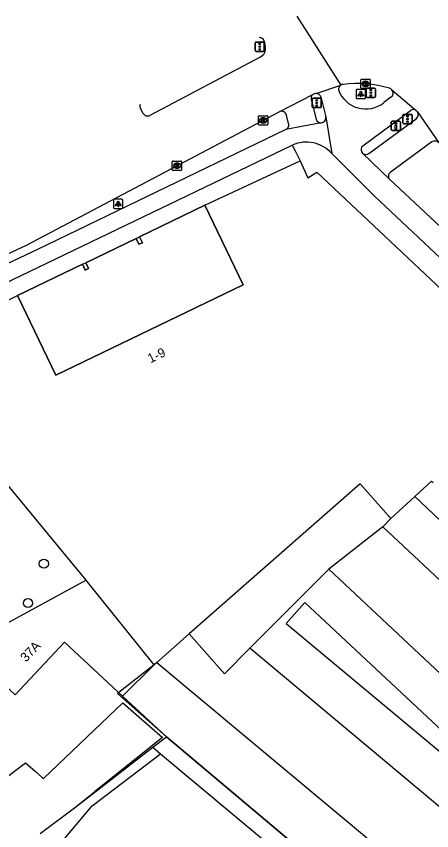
# Model space of a CAD drawing. Extents: x 160107 to 160928, y 382056 to 382918.
# Drawn here: x 160821.8 to 160866.4, y 382827.7 to 382915.3 of the extents above; entities that cross this region are included whole.
import ezdxf

# ---------------------------------------------------------------- set-up
doc = ezdxf.new("R2010")
doc.units = 0
for name, color, linetype in [('IMGEO_Boom', 7, 'Continuous'), ('IMGEO_Drukknoppaal', 7, 'Continuous'), ('IMGEO_Fietspad_gesloten', 7, 'Continuous'), ('IMGEO_Hek', 7, 'Continuous'), ('IMGEO_Kolk', 7, 'Continuous'), ('IMGEO_Lichtpunt', 7, 'Continuous'), ('IMGEO_Muur', 7, 'Continuous'), ('IMGEO_Pand', 7, 'Continuous'), ('IMGEO_Pand_nummerreeks', 7, 'Continuous'), ('IMGEO_Pand_overbouw', 7, 'Continuous'), ('IMGEO_Parkeervlak_open', 7, 'Continuous'), ('IMGEO_Rijbaan_lokaal_gesloten', 7, 'Continuous'), ('IMGEO_Rijbaan_lokaal_open', 7, 'Continuous'), ('IMGEO_Verkeersregelinstallatiepaal', 7, 'Continuous'), ('IMGEO_Voetpad_gesloten', 7, 'Continuous'), ('IMGEO_Voetpad_open', 7, 'Continuous')]:
    doc.layers.add(name, color=color, linetype=linetype)

msp = doc.modelspace()

# ---------------------------------------------------------------- linework, layer by layer
at = {"layer": 'IMGEO_Boom'}
for centre in [(160824.732, 382856.436), (160823.02, 382852.195)]:
    msp.add_circle(centre, 0.489, dxfattribs=at)
at = {"layer": 'IMGEO_Drukknoppaal'}
for p, q in [((160862.088, 382903.149), (160862.088, 382903.949)), ((160862.088, 382903.949), (160862.088, 382903.149)), ((160862.188, 382904.049), (160862.978, 382904.049)), ((160862.978, 382904.049), (160862.188, 382904.049)), ((160863.078, 382903.949), (160863.078, 382903.149)), ((160863.078, 382903.149), (160863.078, 382903.949)), ((160862.978, 382903.049), (160862.188, 382903.049)), ((160862.188, 382903.049), (160862.978, 382903.049))]:
    msp.add_line(p, q, dxfattribs=at)
msp.add_lwpolyline([(160862.658, 382903.674), (160862.658, 382903.174), (160862.508, 382903.174), (160862.508, 382903.674), (160862.658, 382903.674)], dxfattribs=at)
msp.add_circle((160862.583, 382903.839), 0.085, dxfattribs=at)
for centre, start, end in [((160862.188, 382903.949), 90, 180), ((160862.188, 382903.949), 90, 180), ((160862.978, 382903.949), 0, 90), ((160862.978, 382903.949), 360, 90), ((160862.188, 382903.149), 180, 270), ((160862.188, 382903.149), 180, 270), ((160862.978, 382903.149), 270, 0), ((160862.978, 382903.149), 270, 0)]:
    msp.add_arc(centre, 0.1, start, end, dxfattribs=at)
at = {"layer": 'IMGEO_Fietspad_gesloten'}
for points in [[(160854.521, 382906.665), (160855.067, 382904.509)], [(160862.061, 382906.639), (160861.286, 382906.048)], [(160855.067, 382904.509), (160855.706, 382900.56)], [(160859.033, 382901.418), (160864.171, 382905.21)], [(160854.566, 382903.866), (160850.751, 382903.174)], [(160850.751, 382903.174), (160824.044, 382890.246), (160820.773, 382888.699), (160818.211, 382887.624)], [(160820.429, 382886.565), (160851.435, 382901.477)], [(160907.683, 382851.452), (160880.807, 382876.637), (160876.3, 382880.906), (160860.259, 382896.037), (160855.706, 382900.56)], [(160859.046, 382900.582), (160858.953, 382900.672)], [(160861.894, 382897.82), (160859.046, 382900.582)], [(160908.09, 382854.364), (160881.279, 382879.654), (160861.894, 382897.82)]]:
    msp.add_lwpolyline(points, dxfattribs=at)
for centre, radius, start, end in [((160856.968, 382907.472), 0.546, 121.21267, 184.94604), ((160854.005, 382906.491), 0.545, 18.66756, 87.88894), ((160859.346, 382908.471), 3.104, 199.70196, 308.67201), ((160861.744, 382907.076), 0.54, 305.92504, 39.64461), ((160864.467, 382904.762), 0.537, 54.27107, 123.47496), ((160854.456, 382904.468), 0.612, 280.35139, 3.8), ((160852.947, 382898.114), 3.687, 41.55965, 114.20503), ((160859.371, 382901.004), 0.534, 129.28473, 218.47342)]:
    msp.add_arc(centre, radius, start, end, dxfattribs=at)
at = {"layer": 'IMGEO_Hek'}
for points in [[(160836.59, 382845.555), (160832.666, 382842.466)], [(160832.666, 382842.466), (160837.913, 382837.822)]]:
    msp.add_lwpolyline(points, dxfattribs=at)
at = {"layer": 'IMGEO_Kolk'}
for p, q in [((160858.832, 382907.642), (160858.832, 382908.494)), ((160858.907, 382908.568), (160859.759, 382908.568)), ((160859.32, 382908.348), (160859.345, 382908.348)), ((160859.833, 382908.494), (160859.833, 382907.642)), ((160859.759, 382907.568), (160858.907, 382907.568)), ((160859.343, 382907.788), (160859.318, 382907.788)), ((160847.815, 382903.71), (160847.815, 382904.562)), ((160847.89, 382904.636), (160848.742, 382904.636)), ((160848.303, 382904.416), (160848.328, 382904.416)), ((160848.816, 382904.562), (160848.816, 382903.71)), ((160848.742, 382903.636), (160847.89, 382903.636)), ((160848.326, 382903.856), (160848.301, 382903.856)), ((160838.548, 382898.837), (160838.548, 382899.689)), ((160838.623, 382899.763), (160839.475, 382899.763)), ((160839.036, 382899.543), (160839.061, 382899.543)), ((160839.549, 382899.689), (160839.549, 382898.837)), ((160839.475, 382898.763), (160838.623, 382898.763)), ((160839.059, 382898.983), (160839.034, 382898.983))]:
    msp.add_line(p, q, dxfattribs=at)
for points in [[(160858.832, 382907.642), (160858.832, 382908.494)], [(160858.907, 382908.568), (160859.759, 382908.568)], [(160859.153, 382908.268), (160859.276, 382908.268), (160859.276, 382908.117), (160859.406, 382908.268), (160859.57, 382908.268), (160859.424, 382908.117), (160859.577, 382907.868), (160859.425, 382907.868), (160859.34, 382908.032), (160859.276, 382907.965), (160859.276, 382907.868), (160859.153, 382907.868), (160859.153, 382908.268)], [(160859.833, 382908.494), (160859.833, 382907.642)], [(160859.759, 382907.568), (160858.907, 382907.568)], [(160847.815, 382903.71), (160847.815, 382904.562)], [(160847.89, 382904.636), (160848.742, 382904.636)], [(160848.816, 382904.562), (160848.816, 382903.71)], [(160848.742, 382903.636), (160847.89, 382903.636)], [(160848.136, 382904.336), (160848.259, 382904.336), (160848.259, 382904.185), (160848.389, 382904.336), (160848.553, 382904.336), (160848.407, 382904.185), (160848.56, 382903.936), (160848.408, 382903.936), (160848.323, 382904.1), (160848.259, 382904.033), (160848.259, 382903.936), (160848.136, 382903.936), (160848.136, 382904.336)], [(160838.548, 382898.837), (160838.548, 382899.689)], [(160838.623, 382899.763), (160839.475, 382899.763)], [(160838.869, 382899.463), (160838.992, 382899.463), (160838.992, 382899.312), (160839.122, 382899.463), (160839.286, 382899.463), (160839.14, 382899.312), (160839.293, 382899.063), (160839.141, 382899.063), (160839.056, 382899.227), (160838.992, 382899.16), (160838.992, 382899.063), (160838.869, 382899.063), (160838.869, 382899.463)], [(160839.549, 382899.689), (160839.549, 382898.837)], [(160839.475, 382898.763), (160838.623, 382898.763)]]:
    msp.add_lwpolyline(points, dxfattribs=at)
for centre, start, end in [((160858.909, 382908.492), 91.55205, 178.44795), ((160858.909, 382908.492), 91.55205, 178.44795), ((160859.757, 382908.492), 1.55205, 88.44795), ((160859.757, 382908.492), 1.55205, 88.44795), ((160858.909, 382907.644), 181.55205, 268.44795), ((160858.909, 382907.644), 181.55205, 268.44795), ((160859.757, 382907.644), 271.55205, 358.44795), ((160859.757, 382907.644), 271.55205, 358.44795), ((160847.892, 382904.56), 91.55205, 178.44795), ((160847.892, 382904.56), 91.55205, 178.44795), ((160848.74, 382904.56), 1.55205, 88.44795), ((160848.74, 382904.56), 1.55205, 88.44795), ((160847.892, 382903.712), 181.55205, 268.44795), ((160847.892, 382903.712), 181.55205, 268.44795), ((160848.74, 382903.712), 271.55205, 358.44795), ((160848.74, 382903.712), 271.55205, 358.44795), ((160838.625, 382899.687), 91.55205, 178.44795), ((160838.625, 382899.687), 91.55205, 178.44795), ((160839.473, 382899.687), 1.55205, 88.44795), ((160839.473, 382899.687), 1.55205, 88.44795), ((160838.625, 382898.839), 181.55205, 268.44795), ((160838.625, 382898.839), 181.55205, 268.44795), ((160839.473, 382898.839), 271.55205, 358.44795), ((160839.473, 382898.839), 271.55205, 358.44795)]:
    msp.add_arc(centre, 0.0765, start, end, dxfattribs=at)
for centre, major_axis, ratio, start_param, end_param in [((160859.319, 382908.068), (-0.387, 0.002), 0.722429, 4.712389, 7.853982), ((160859.344, 382908.068), (-0.39, 0.002), 0.717154, 1.570796, 4.712389), ((160848.302, 382904.136), (-0.387, 0.002), 0.722429, 4.712389, 7.853982), ((160848.327, 382904.136), (-0.39, 0.002), 0.717154, 1.570796, 4.712389), ((160839.035, 382899.263), (-0.387, 0.002), 0.722429, 4.712389, 7.853982), ((160839.06, 382899.263), (-0.39, 0.002), 0.717154, 1.570796, 4.712389)]:
    msp.add_ellipse(centre, major_axis=major_axis, ratio=ratio, start_param=start_param, end_param=end_param, dxfattribs=at)
at = {"layer": 'IMGEO_Lichtpunt'}
for p, q in [((160858.312, 382907.38), (160858.312, 382906.573)), ((160858.312, 382907.38), (160858.312, 382906.573)), ((160859.214, 382907.475), (160858.406, 382907.475)), ((160859.214, 382907.475), (160858.406, 382907.475)), ((160859.308, 382906.573), (160859.308, 382907.38)), ((160859.308, 382906.573), (160859.308, 382907.38)), ((160858.406, 382906.479), (160859.214, 382906.479)), ((160858.406, 382906.479), (160859.214, 382906.479)), ((160833.134, 382895.651), (160832.326, 382895.651)), ((160833.134, 382895.651), (160832.326, 382895.651)), ((160832.232, 382895.556), (160832.232, 382894.749)), ((160832.232, 382895.556), (160832.232, 382894.749)), ((160833.228, 382894.749), (160833.228, 382895.556)), ((160833.228, 382894.749), (160833.228, 382895.556)), ((160832.326, 382894.655), (160833.134, 382894.655)), ((160832.326, 382894.655), (160833.134, 382894.655))]:
    msp.add_line(p, q, dxfattribs=at)
for points in [[(160858.686, 382907.044), (160858.725, 382907.016), (160858.537, 382906.754), (160858.499, 382906.781), (160858.686, 382907.044)], [(160858.788, 382906.996), (160858.835, 382906.996), (160858.835, 382906.674), (160858.788, 382906.674), (160858.788, 382906.996)], [(160858.898, 382907.016), (160858.936, 382907.043), (160859.123, 382906.781), (160859.084, 382906.753), (160858.898, 382907.016)], [(160832.606, 382895.22), (160832.645, 382895.192), (160832.457, 382894.93), (160832.419, 382894.957), (160832.606, 382895.22)], [(160832.708, 382895.172), (160832.755, 382895.172), (160832.755, 382894.85), (160832.708, 382894.85), (160832.708, 382895.172)], [(160832.818, 382895.192), (160832.856, 382895.219), (160833.043, 382894.957), (160833.004, 382894.929), (160832.818, 382895.192)]]:
    msp.add_lwpolyline(points, dxfattribs=at)
for centre in [(160858.811, 382907.178), (160832.731, 382895.354)]:
    msp.add_circle(centre, 0.0994, dxfattribs=at)
for centre, start, end in [((160858.406, 382907.38), 90, 180), ((160858.406, 382907.38), 90, 180), ((160859.214, 382907.38), 0, 90), ((160859.214, 382907.38), 0, 90), ((160858.406, 382906.573), 180, 270), ((160858.406, 382906.573), 180, 270), ((160859.214, 382906.573), 270, 0), ((160859.214, 382906.573), 270, 360), ((160832.326, 382895.556), 90, 180), ((160832.326, 382895.556), 90, 180), ((160833.134, 382895.556), 0, 90), ((160833.134, 382895.556), 0, 90), ((160832.326, 382894.749), 180, 270), ((160832.326, 382894.749), 180, 270), ((160833.134, 382894.749), 270, 0), ((160833.134, 382894.749), 270, 360)]:
    msp.add_arc(centre, 0.0946, start, end, dxfattribs=at)
at = {"layer": 'IMGEO_Muur'}
for points in [[(160837.913, 382837.822), (160861.483, 382817.978)], [(160828.158, 382830.281), (160836.442, 382836.685)], [(160836.442, 382836.685), (160837.27, 382835.986)]]:
    msp.add_lwpolyline(points, dxfattribs=at)
at = {"layer": 'IMGEO_Pand'}
for points in [[(160842.054, 382895.005), (160852.299, 382899.776)], [(160852.299, 382899.776), (160853.109, 382897.965), (160854.082, 382898.574), (160875.468, 382878.428)], [(160842.054, 382895.005), (160846.177, 382886.446), (160826.022, 382876.74), (160821.899, 382885.299)], [(160834.66, 382891.435), (160835.021, 382891.609)], [(160834.66, 382891.435), (160834.964, 382890.804), (160835.324, 382890.978), (160835.021, 382891.609)], [(160828.874, 382888.653), (160829.235, 382888.827)], [(160828.874, 382888.653), (160829.178, 382888.022), (160829.538, 382888.196), (160829.235, 382888.827)], [(160811.707, 382880.282), (160821.899, 382885.299)], [(160829.281, 382854.653), (160817.486, 382868.952), (160817.086, 382869.61)], [(160862.028, 382861.283), (160858.731, 382865.029), (160840.366, 382848.876)], [(160866.606, 382865.137), (160866.424, 382865.309), (160864.631, 382863.667)], [(160864.631, 382863.667), (160862.028, 382861.283)], [(160829.281, 382854.653), (160818.676, 382848.872)], [(160836.59, 382845.555), (160829.388, 382854.523), (160829.281, 382854.653)], [(160840.366, 382848.876), (160836.872, 382845.803)], [(160816.125, 382847.481), (160821.642, 382842.326), (160826.951, 382848.006), (160833.184, 382842.181)], [(160836.872, 382845.803), (160836.59, 382845.555)], [(160833.184, 382842.181), (160836.59, 382845.555)], [(160813.461, 382827.975), (160822.775, 382834.996), (160823.797, 382834.101), (160824.507, 382833.479), (160824.682, 382833.325), (160833.239, 382841.46), (160837.501, 382837.727), (160830.181, 382831.893)], [(160826.177, 382825.89), (160829.915, 382830.38), (160837.27, 382835.986)], [(160837.27, 382835.986), (160869.624, 382808.98), (160869.704, 382809.079), (160878.006, 382802.366)], [(160824.354, 382827.401), (160828.158, 382830.281), (160830.181, 382831.893)]]:
    msp.add_lwpolyline(points, dxfattribs=at)
at = {"layer": 'IMGEO_Pand_overbouw'}
msp.add_lwpolyline([(160834.66, 382891.435), (160829.235, 382888.827), (160829.538, 382888.196), (160829.178, 382888.022), (160828.874, 382888.653), (160821.899, 382885.299), (160826.022, 382876.74), (160846.177, 382886.446), (160842.054, 382895.005), (160835.021, 382891.609), (160835.324, 382890.978), (160834.964, 382890.804)], close=True, dxfattribs=at)
at = {"layer": 'IMGEO_Parkeervlak_open'}
for points in [[(160885.141, 382837.99), (160888.24, 382841.299), (160864.631, 382863.667)], [(160850.806, 382850.011), (160873.79, 382830.829), (160874.703, 382831.786), (160852.792, 382852.262), (160850.806, 382850.011)]]:
    msp.add_lwpolyline(points, dxfattribs=at)
at = {"layer": 'IMGEO_Rijbaan_lokaal_gesloten'}
for points in [[(160851.95, 382915.343), (160856.685, 382907.939)], [(160848.428, 382912.674), (160848.544, 382912.085)], [(160848.047, 382910.983), (160836.138, 382904.677)], [(160854.025, 382907.035), (160856.685, 382907.939)], [(160862.16, 382907.421), (160864.781, 382905.198)], [(160850.096, 382905.089), (160853.659, 382906.91)], [(160835.422, 382904.898), (160835.125, 382905.413)], [(160817.861, 382888.575), (160820.869, 382889.792), (160822.883, 382890.72), (160850.096, 382905.089)], [(160864.911, 382905.064), (160867.193, 382901.716)]]:
    msp.add_lwpolyline(points, dxfattribs=at)
for centre, radius, start, end in [((160847.918, 382912.533), 0.521, 94.83979, 94.89905), ((160847.923, 382912.529), 0.525, 16.03297, 95.35477), ((160847.584, 382911.855), 0.987, 297.95346, 13.49597), ((160856.96, 382907.486), 0.53, 96.20797, 121.29154), ((160858.395, 382895.807), 12.297, 73.45946, 96.96958), ((160854.008, 382906.487), 0.548, 88.19084, 129.52231), ((160861.746, 382907.081), 0.536, 39.45108, 73.77189), ((160835.521, 382905.677), 0.476, 156.9739, 213.70009), ((160835.89, 382905.145), 0.529, 207.77626, 297.9171), ((160864.48, 382904.776), 0.518, 33.74544, 54.51845)]:
    msp.add_arc(centre, radius, start, end, dxfattribs=at)
at = {"layer": 'IMGEO_Rijbaan_lokaal_open'}
for points in [[(160861.201, 382860.414), (160855.371, 382855.843)], [(160885.141, 382837.99), (160861.201, 382860.414)], [(160855.371, 382855.843), (160882.262, 382830.641), (160875.839, 382823.088), (160846.893, 382847.344)], [(160846.893, 382847.344), (160844.141, 382844.584), (160840.366, 382848.876)], [(160836.872, 382845.803), (160865.06, 382822.273), (160865.612, 382822.936), (160869.325, 382819.842)], [(160837.913, 382837.822), (160833.184, 382842.181)], [(160836.442, 382836.685), (160837.913, 382837.822)], [(160830.181, 382831.893), (160830.204, 382831.863), (160836.442, 382836.685)]]:
    msp.add_lwpolyline(points, dxfattribs=at)
at = {"layer": 'IMGEO_Verkeersregelinstallatiepaal'}
for p, q in [((160847.449, 382911.671), (160847.449, 382912.471)), ((160847.449, 382912.471), (160847.449, 382911.671)), ((160847.549, 382912.571), (160848.339, 382912.571)), ((160848.339, 382912.571), (160847.549, 382912.571)), ((160848.439, 382912.471), (160848.439, 382911.671)), ((160848.439, 382911.671), (160848.439, 382912.471)), ((160848.339, 382911.571), (160847.549, 382911.571)), ((160847.549, 382911.571), (160848.339, 382911.571)), ((160859.4, 382906.713), (160859.4, 382907.513)), ((160859.4, 382907.513), (160859.4, 382906.713)), ((160859.5, 382907.613), (160860.29, 382907.613)), ((160860.29, 382907.613), (160859.5, 382907.613)), ((160860.39, 382907.513), (160860.39, 382906.713)), ((160860.39, 382906.713), (160860.39, 382907.513)), ((160853.575, 382905.615), (160853.575, 382906.415)), ((160853.575, 382906.415), (160853.575, 382905.615)), ((160853.675, 382906.515), (160854.465, 382906.515)), ((160854.465, 382906.515), (160853.675, 382906.515)), ((160854.565, 382906.415), (160854.565, 382905.615)), ((160854.565, 382905.615), (160854.565, 382906.415)), ((160860.29, 382906.613), (160859.5, 382906.613)), ((160859.5, 382906.613), (160860.29, 382906.613)), ((160854.465, 382905.515), (160853.675, 382905.515)), ((160853.675, 382905.515), (160854.465, 382905.515)), ((160863.336, 382903.888), (160863.336, 382904.688)), ((160863.336, 382904.688), (160863.336, 382903.888)), ((160863.436, 382904.788), (160864.226, 382904.788)), ((160864.226, 382904.788), (160863.436, 382904.788)), ((160864.326, 382904.688), (160864.326, 382903.888)), ((160864.326, 382903.888), (160864.326, 382904.688)), ((160864.226, 382903.788), (160863.436, 382903.788)), ((160863.436, 382903.788), (160864.226, 382903.788))]:
    msp.add_line(p, q, dxfattribs=at)
for centre in [(160847.944, 382912.361), (160847.944, 382912.071), (160847.944, 382911.781), (160859.895, 382907.403), (160859.895, 382907.113), (160854.07, 382906.305), (160859.895, 382906.823), (160854.07, 382906.015), (160854.07, 382905.725), (160863.831, 382904.578), (160863.831, 382904.288), (160863.831, 382903.998)]:
    msp.add_circle(centre, 0.085, dxfattribs=at)
for centre, start, end in [((160847.549, 382912.471), 90, 180), ((160847.549, 382912.471), 90, 180), ((160848.339, 382912.471), 0, 90), ((160848.339, 382912.471), 360, 90), ((160847.549, 382911.671), 180, 270), ((160847.549, 382911.671), 180, 270), ((160848.339, 382911.671), 270, 0), ((160848.339, 382911.671), 270, 0), ((160859.5, 382907.513), 90, 180), ((160859.5, 382907.513), 90, 180), ((160860.29, 382907.513), 0, 90), ((160860.29, 382907.513), 360, 90), ((160853.675, 382906.415), 90, 180), ((160853.675, 382906.415), 90, 180), ((160854.465, 382906.415), 0, 90), ((160854.465, 382906.415), 360, 90), ((160859.5, 382906.713), 180, 270), ((160859.5, 382906.713), 180, 270), ((160860.29, 382906.713), 270, 0), ((160860.29, 382906.713), 270, 0), ((160853.675, 382905.615), 180, 270), ((160853.675, 382905.615), 180, 270), ((160854.465, 382905.615), 270, 0), ((160854.465, 382905.615), 270, 0), ((160863.436, 382904.688), 90, 180), ((160863.436, 382904.688), 90, 180), ((160864.226, 382904.688), 0, 90), ((160864.226, 382904.688), 360, 90), ((160863.436, 382903.888), 180, 270), ((160863.436, 382903.888), 180, 270), ((160864.226, 382903.888), 270, 0), ((160864.226, 382903.888), 270, 0)]:
    msp.add_arc(centre, 0.1, start, end, dxfattribs=at)
at = {"layer": 'IMGEO_Voetpad_gesloten'}
for points in [[(160853.472, 382906.389), (160854.022, 382904.273)], [(160851.039, 382903.808), (160850.839, 382904.711)], [(160859.684, 382900.573), (160864.77, 382904.321)], [(160866.438, 382901.827), (160861.976, 382898.535)]]:
    msp.add_lwpolyline(points, dxfattribs=at)
for centre, radius, start, end in [((160854.005, 382906.492), 0.543, 129.58061, 190.93071), ((160850.297, 382904.565), 0.561, 15.08102, 110.9897), ((160864.432, 382904.77), 0.562, 307.00121, 31.50816), ((160850.59, 382903.63), 0.483, 289.47192, 21.6674), ((160854.541, 382904.4), 0.535, 193.74682, 272.64831), ((160866.756, 382901.366), 0.56, 38.70173, 124.57086), ((160859.371, 382901.002), 0.531, 232.26569, 306.11792), ((160862.26, 382898.14), 0.487, 125.7592, 221.156)]:
    msp.add_arc(centre, radius, start, end, dxfattribs=at)
at = {"layer": 'IMGEO_Voetpad_open'}
for points in [[(160851.435, 382901.477), (160851.784, 382900.791), (160852.299, 382899.776)], [(160835.021, 382891.609), (160842.054, 382895.005)], [(160829.235, 382888.827), (160834.66, 382891.435)], [(160821.899, 382885.299), (160828.874, 382888.653)], [(160861.201, 382860.414), (160862.028, 382861.283)], [(160846.893, 382847.344), (160855.371, 382855.843)], [(160865.195, 382814.885), (160861.483, 382817.978), (160837.913, 382837.822)], [(160836.442, 382836.685), (160837.27, 382835.986)]]:
    msp.add_lwpolyline(points, dxfattribs=at)

# ---------------------------------------------------------------- texts
at = {"layer": 'IMGEO_Pand_nummerreeks'}
for s, rotation, p in [('1-9', 25.71435, (160836.188, 382877.995)), ('37A', 46.93097, (160822.827, 382845.791))]:
    msp.add_text(s, height=1, rotation=rotation, dxfattribs=at).set_placement(p)

doc.saveas('drawing.dxf')
